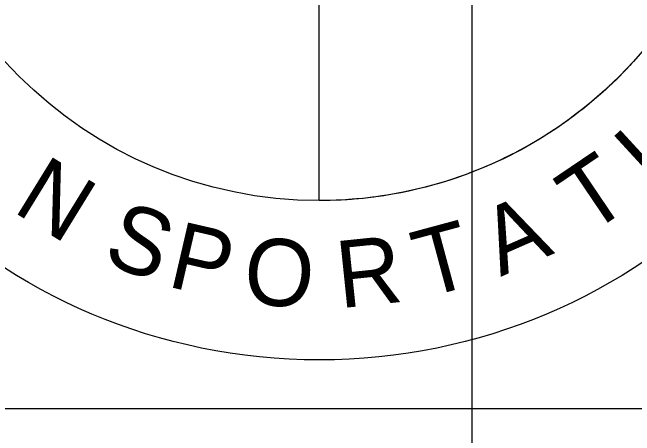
# Model space of a CAD drawing. Extents: x 0 to 1.42, y 0 to 0.92.
# Drawn here: x 1.35536 to 1.382, y 0.16135 to 0.17946 of the extents above; entities that cross this region are included whole.
import ezdxf

# ---------------------------------------------------------------- set-up
doc = ezdxf.new("R2010")
doc.units = 0
doc.layers.add('#plot_layout', color=7, linetype='Continuous')
doc.layers.add('P_ODOT_PLAN_TBlock', color=7, linetype='Continuous')

msp = doc.modelspace()

# ---------------------------------------------------------------- linework, layer by layer
at = {"layer": '#plot_layout'}
msp.add_lwpolyline([(0.08333250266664, 0.4583166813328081), (1.3750325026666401, 0.4583166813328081), (1.3750325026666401, 0.062499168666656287), (0.08333250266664, 0.062499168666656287)], close=True, dxfattribs=at)
at = {"layer": 'P_ODOT_PLAN_TBlock'}
msp.add_line((1.1208776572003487, 0.16250000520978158), (1.395866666, 0.16250000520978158), dxfattribs=at)
msp.add_lwpolyline([(1.3820236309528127, 0.17743546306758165), (1.3818720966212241, 0.1772688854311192), (1.3818014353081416, 0.17719304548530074), (1.381779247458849, 0.17716927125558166), (1.3816620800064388, 0.17704483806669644), (1.3814927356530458, 0.17686976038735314), (1.3813627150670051, 0.17673816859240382), (1.3812892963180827, 0.1766650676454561), (1.3811747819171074, 0.17655268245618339), (1.381126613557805, 0.17650598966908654), (1.3811184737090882, 0.17649827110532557), (1.3811063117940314, 0.17648641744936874), (1.381023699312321, 0.1764073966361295), (1.3809089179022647, 0.17629956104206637), (1.3807639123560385, 0.17616525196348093), (1.3806362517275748, 0.17604984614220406), (1.3803574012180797, 0.1758052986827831), (1.3799646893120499, 0.17547626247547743), (1.3797770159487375, 0.17532574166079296), (1.3796692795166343, 0.17524117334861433), (1.3795609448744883, 0.17515729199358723), (1.379317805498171, 0.17497424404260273), (1.3791520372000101, 0.17485281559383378), (1.3787237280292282, 0.1745525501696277), (1.3784501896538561, 0.1743700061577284), (1.3783557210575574, 0.17430861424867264), (1.3782963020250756, 0.17427042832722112), (1.3781648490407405, 0.17418711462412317), (1.3781067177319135, 0.1741505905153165), (1.3776839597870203, 0.17389550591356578), (1.3774352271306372, 0.17375251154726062), (1.3773420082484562, 0.17370023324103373), (1.3773234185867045, 0.17368989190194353), (1.3770922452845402, 0.17356339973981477), (1.3768565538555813, 0.17343952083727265), (1.3767560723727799, 0.1733878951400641), (1.37653542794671, 0.17327730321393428), (1.3764703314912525, 0.17324536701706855), (1.3764006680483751, 0.1732115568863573), (1.3763763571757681, 0.1731998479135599), (1.3763661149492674, 0.17319493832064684), (1.3763625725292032, 0.17319323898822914), (1.3762409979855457, 0.17313589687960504), (1.3758396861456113, 0.1729525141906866), (1.3756627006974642, 0.17287548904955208), (1.3755281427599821, 0.17281843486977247), (1.375356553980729, 0.17274742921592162), (1.3750222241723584, 0.17261519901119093), (1.3747848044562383, 0.17252581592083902), (1.374665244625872, 0.17248222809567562), (1.3745451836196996, 0.17243958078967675), (1.374339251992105, 0.17236818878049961), (1.3741324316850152, 0.17229947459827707), (1.3737130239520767, 0.17216826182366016), (1.37297769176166, 0.17196492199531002), (1.372510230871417, 0.1718525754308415), (1.3723322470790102, 0.1718132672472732), (1.3719849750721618, 0.1717412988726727), (1.371632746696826, 0.17167668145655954), (1.371408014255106, 0.17163879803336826), (1.3711823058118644, 0.1716036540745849), (1.3708286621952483, 0.17155443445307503), (1.3707799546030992, 0.17154823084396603), (1.370371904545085, 0.17150133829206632), (1.3700868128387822, 0.1714740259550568), (1.3699220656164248, 0.17146032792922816), (1.3699072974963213, 0.17145925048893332), (1.3698676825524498, 0.17145614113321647), (1.3697577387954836, 0.17144819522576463), (1.3696967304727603, 0.1714440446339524), (1.3696734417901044, 0.17144254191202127), (1.3694390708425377, 0.1714290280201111), (1.369356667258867, 0.17142479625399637), (1.3692241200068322, 0.17141905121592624), (1.368969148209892, 0.17141037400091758), (1.3688103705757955, 0.1714071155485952), (1.3686053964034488, 0.1714047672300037), (1.3685323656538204, 0.17140459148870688), (1.3684992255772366, 0.17140455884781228), (1.3684992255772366, 0.1799006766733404)], dxfattribs=at)
for radius in [0.025000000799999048, 0.018178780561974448]:
    msp.add_circle((1.3684992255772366, 0.18958333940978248), radius, dxfattribs=at)

# ---------------------------------------------------------------- texts
for s, height, rotation, p in [('I', 0.0028694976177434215, 42.57913222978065, (1.3828115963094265, 0.17182533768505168)), ('T', 0.0028694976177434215, 34.07346227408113, (1.3800276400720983, 0.16990374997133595)), ('N', 0.002869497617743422, 328.40862769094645, (1.3553187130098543, 0.1709697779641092)), ('A', 0.0028694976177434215, 23.606808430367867, (1.376260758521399, 0.16813691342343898)), ('S', 0.0028694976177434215, 339.5081090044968, (1.3591486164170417, 0.16878053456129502)), ('P', 0.0028694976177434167, 346.9746918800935, (1.3619311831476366, 0.16774183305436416)), ('T', 0.0028694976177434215, 15.101138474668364, (1.3730033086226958, 0.16722481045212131)), ('O', 0.0028694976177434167, 355.3787969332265, (1.3651939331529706, 0.16701642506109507)), ('R', 0.0028694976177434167, 5.939202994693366, (1.3693858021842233, 0.16679289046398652))]:
    msp.add_text(s, height=height, rotation=rotation, dxfattribs=at).set_placement(p)

doc.saveas('drawing.dxf')
